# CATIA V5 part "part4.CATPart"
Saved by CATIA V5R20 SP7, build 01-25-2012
Part number: squelette pied gauche
Bounding box of the stored display mesh (mm): x 4.042 to 98.781, y -95 to -75, z -49.894 to 26.474
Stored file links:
  F:\Travaux\Modélisations\CFAO_2011\CFAO_2011_MMS\CFAO_2011_MMS_DONE\CFAO_2011_MMS_jboiteux\Catia\part4.CATPart
  U:\finthinkmotion\stepper.CATProduct
  F:\Travaux\Modélisations\CFAO_2011\CFAO_2011_MMS\CFAO_2011_MMS_DONE\CFAO_2011_MMS_jboiteux\Catia\Part1.CATPart
  F:\Travaux\Modélisations\CFAO_2011\CFAO_2011_MMS\CFAO_2011_MMS_DONE\CFAO_2011_MMS_jboiteux\Catia\pied avant.CATPart
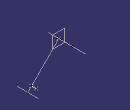
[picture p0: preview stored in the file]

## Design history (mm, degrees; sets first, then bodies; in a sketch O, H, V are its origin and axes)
Parameters
  longueurpied = 108 mm
Set1
  Plane1: linked copy from another document
  Plane2: linked copy from another document
  Point1: linked copy from another document
Body1 (main body)
  Line1: stored without definition
  Point2: stored without definition
  Line2: type PtDir, RefPoint Point2, Direction Line1, Start 0, End 108 {= longueurpied}
  Line3: stored without definition
  Point3: stored without definition
  Line4: type PtDir, RefPoint Point3, Direction Line3, Start -5, End 5
  Point4: stored without definition
  Plane3: type OffsetPt, RefPlane zx-plane, RefPoint Point4
  Point5: stored without definition
  Point6: stored without definition
  Plane4: stored without definition
  Line5: type Angle, RefPoint Point6, Curve Line2, Support Plane1, Start 0, End -30, Angle 90
  Point7: type OnCurve, Support Line2, Length 13
  Plane5: stored without definition
  Line6: type Angle, RefPoint Point7, Curve Line2, Support Plane1, Start 0, End -10, Angle 90
  Plane6: stored without definition
  Point8: type OnCurve, Support Line6, Ratio 0
  Plane7: stored without definition
  Plane8: type Normal, Curve Line2, RefPoint vertex of Line2
  Plane9: type OffsetPt, RefPlane Plane2, RefPoint Point1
